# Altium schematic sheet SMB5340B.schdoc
size 127 x 101 mm
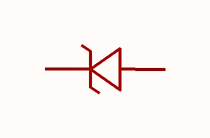
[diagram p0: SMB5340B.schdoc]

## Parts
D?  smb5340b  [SMBG_L4.3-W3.6-LS6.2-RD]  (value not drawn)

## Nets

Not connected (* = marked no-connect by the designer): D? 1(K) 2(A)

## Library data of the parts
D? = smb5340b: 二极管配置:1个独立式;稳压值(标称值):6V;稳压值(范围值):-;耗散功率(Pd):5W;; Manufacturer: CJ(江苏长电/长晶); AddInBom: yes; ModelId: 8e07069208fb411d84761ad3f1395462; ModelTransform: 244.094,142.5194,0,0,0,0,0,0,0; Diode Configuration: 1个独立式; Zener Voltage(Nom): 6V; Reverse Leakage Current (Ir): 1uA; Pd - Power Dissipation: 5W; Impedance(Zzt): 1Ω; Impedance(Zzk): 300Ω; Operating Junction Temperature Range: -55℃~+150℃; Tolerance: ±5%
